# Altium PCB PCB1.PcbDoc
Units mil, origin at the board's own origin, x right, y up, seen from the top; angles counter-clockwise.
Board outline 6000 x 4000 mil, 2 copper layers (Top Layer, Bottom Layer); 1 components, 3 nets, 8 pads, 9 vias.
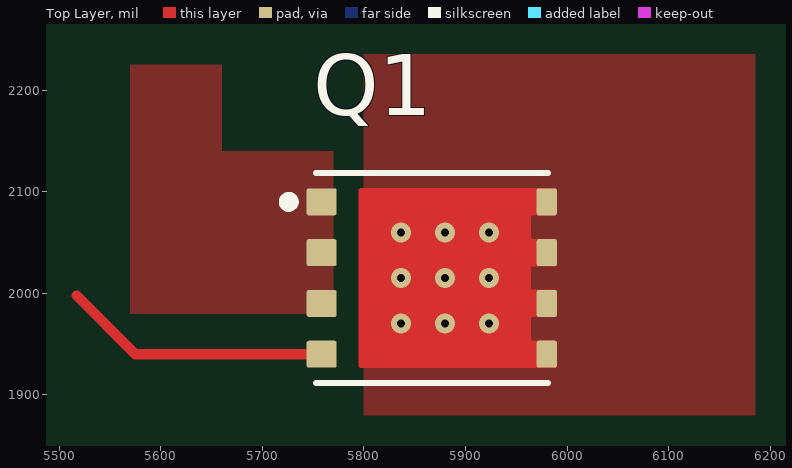
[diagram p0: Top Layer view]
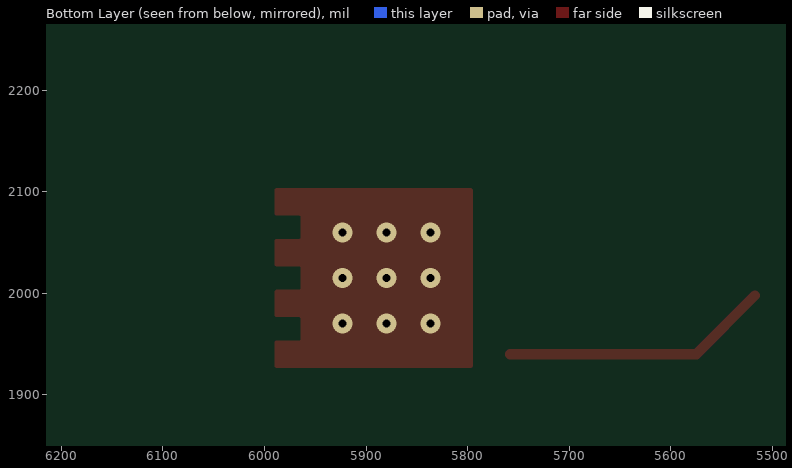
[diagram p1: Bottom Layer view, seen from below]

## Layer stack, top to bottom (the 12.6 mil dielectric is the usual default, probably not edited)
Top Solder: solder mask 0.4, Solder Resist, Dk 3.5
Top Layer: signal copper 1.4
Dielectric 1: dielectric 12.6, FR-4, Dk 4.8
Bottom Layer: signal copper 1.4
Bottom Solder: solder mask 0.4, Solder Resist, Dk 3.5

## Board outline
1000,1000 7000,1000 7000,5000 1000,5000

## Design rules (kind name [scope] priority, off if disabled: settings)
Clearance [All] p1: gap=10 ignorepadtopadclearanceinfootprint=FALSE except(0: Arc-Hole Track-Hole SMDPad-Hole THPad-Hole Via-Hole Fill-Hole Poly-Hole Region-Hole Text-Hole)
MinimumAnnularRing [All] p1: minimumring=4
PolygonConnect [All] p1: thpad.connectstyle=Relief thpad.reliefconductorwidth=10 thpad.reliefentries=4 thpad.polygonreliefangle="90 Angle" thpad.airgapwidth=10 smdpad.connectstyle=Direct smdpad.reliefconductorwidth=10 smdpad.reliefentries=4 smdpad.polygonreliefangle="90 Angle" smdpad.airgapwidth=10 via.connectstyle=Direct via.reliefconductorwidth=10 via.reliefentries=4 via.polygonreliefangle="90 Angle" via.airgapwidth=10
RoomDefinition Sheet1 [InComponentClass('Sheet1')] p1: confinementstyle=ConfineIn formatcopy=TRUE lockcomponents=FALSE outline 5706.81,1900 6001.81,1900 6001.81,2230 5706.81,2230
RoutingVias [All] p1: holewidth=28 width=50 viastyle="Through Hole" minholewidth=28 minwidth=50 maxholewidth=28 maxwidth=50
SolderMaskExpansion [All] p1: expansion=4 istentingtop=FALSE
Width [All] p1: maxlimit=10 minlimit=10 preferedwidth=10
30 further rules are at their usual default settings.

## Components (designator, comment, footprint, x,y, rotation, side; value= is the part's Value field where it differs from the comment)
Q1 "CSD17579Q5A" DQJ0008A-MFG 5866.81,2015 r0 top

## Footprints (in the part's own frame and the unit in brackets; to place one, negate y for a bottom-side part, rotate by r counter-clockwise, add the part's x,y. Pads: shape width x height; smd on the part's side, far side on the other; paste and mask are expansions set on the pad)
DQJ0008A-MFG [mm] "Recommended Land Pattern"
  rrect15% 0.75x0.675 smd paste+0 mask+0: 1(-2.753,1.905) 2(-2.753,0.635) 3(-2.753,-0.635) 4(-2.753,-1.905)
  rrect20% 0.505x0.675 smd paste+0 mask-1000: 5(2.875,-1.905) 6(2.875,-0.635) 7(2.875,0.635) 8(2.875,1.905)
  Top Layer region: -1.773,-2.242 -1.798,-2.236 -1.816,-2.218 -1.823,-2.193 -1.823,-2.193 -1.823,2.193 -1.816,2.218 -1.798,2.236 -1.773,2.242 -1.773,2.242 3.077,2.242 3.102,2.236 3.12,2.218 3.127,2.193 3.127,2.193 3.127,1.617 3.12,1.593 3.102,1.574 3.077,1.568 3.077,1.567 2.522,1.568 2.503,1.564 2.487,1.553 2.476,1.537 2.472,1.517 2.472,1.518 2.472,1.022 2.476,1.003 2.487,0.987 2.503,0.976 2.522,0.972 2.522,0.972 3.077,0.972 3.102,0.966 3.12,0.948 3.127,0.923 3.127,0.923 3.127,0.347 3.123,0.328 3.112,0.312 3.096,0.301 3.077,0.297 3.077,0.298 2.522,0.298 2.503,0.294 2.487,0.283 2.476,0.267 2.472,0.247 2.472,0.248 2.472,-0.248 2.476,-0.267 2.487,-0.283 2.503,-0.294 2.522,-0.298 2.522,-0.298 3.077,-0.298 3.096,-0.301 3.112,-0.312 3.123,-0.328 3.127,-0.347 3.127,-0.347 3.127,-0.923 3.12,-0.948 3.102,-0.966 3.077,-0.972 3.077,-0.972 2.522,-0.972 2.503,-0.976 2.487,-0.987 2.476,-1.003 2.472,-1.023 2.472,-1.022 2.472,-1.518 2.476,-1.537 2.487,-1.553 2.503,-1.564 2.522,-1.568 2.522,-1.568 3.077,-1.568 3.096,-1.571 3.112,-1.582 3.123,-1.598 3.127,-1.617 3.127,-1.617 3.127,-2.193 3.12,-2.218 3.102,-2.236 3.077,-2.242 3.077,-2.242
  silkscreen extent -3.7,-2.63 2.9,2.63, body extent -3,-2.55 3,2.55, height 1.1

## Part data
Q1: library part CMP-0128130-1, "Trans MOSFET N-CH Si 30V 25A 8-Pin VSONP EP T/R", Digikey Part Number=296-49601-1-ND, Drain To Source Breakdown Voltage=30V, Input Capacitance At Vds="796pF @ 15V", Manufacturer="Texas Instruments", Mouser Part Number=595-CSD17579Q5A, Operating Temperature Range="-55°C to +150°C", Power_W=3.1W, Pulse Drain Current=105A, Typ Forward Diode Voltage=0.8V

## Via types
v1: diameter 19.68, hole 7.87, Top Layer to Bottom Layer, tented both sides, 9 vias

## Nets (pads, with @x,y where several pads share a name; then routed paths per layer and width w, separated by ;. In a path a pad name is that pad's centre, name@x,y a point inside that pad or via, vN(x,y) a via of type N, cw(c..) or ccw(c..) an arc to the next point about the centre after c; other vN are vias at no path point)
Drain_Net: Q1.5 Q1.6 Q1.7 Q1.8
  other v1: 5836.42,1970.12 5879.72,1970.12 5923.03,1970.12 5836.42,2015 5879.72,2015 5923.03,2015 5836.42,2059.88 5879.72,2059.88 5923.03,2059.88
Gate_Net: Q1.4 | length 265.3
  Top Layer w10: 5517.12,1997.88 5575,1940 Q1.4
Source_Net: Q1.1 Q1.2 Q1.3

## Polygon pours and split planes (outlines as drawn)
Drain_Net on Top Layer "DRAIN_NET_L01_P001" (solid, pour order 1): 5800,2235 5800,1880 6185,1880 6185,2235
Source_Net on Top Layer "SOURCE_NET_L01_P000" (solid, pour order 0): 5770,1980 5770,2140 5660,2140 5660,2225 5570,2225 5570,1980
